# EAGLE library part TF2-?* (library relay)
SMALL POLARIZED RELAY WITH HIGH SENSITIVITY NAiS Source: http://www.mew-europe.com/.. en_ds_61017_0000.pdf
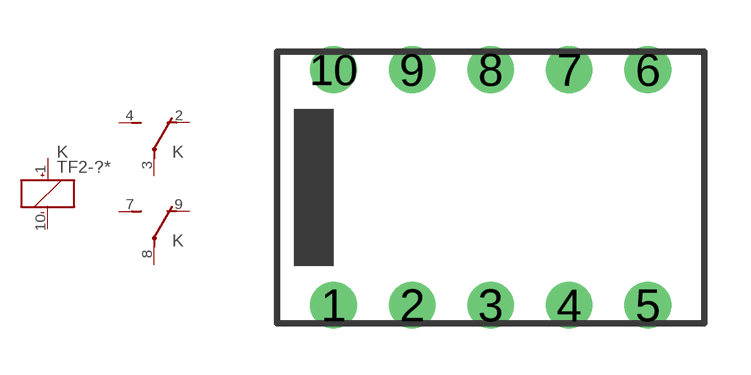
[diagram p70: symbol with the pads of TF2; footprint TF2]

Designator prefix K; gates -=K+- 1=U 2=U

## TF2--3V (OC_FARNELL: unknown; OC_NEWARK: unknown), TF2--4.5V (OC_FARNELL: unknown; OC_NEWARK: unknown), TF2--5V (OC_FARNELL: unknown; OC_NEWARK: unknown), TF2--6V (OC_FARNELL: unknown; OC_NEWARK: unknown), TF2--9V (OC_FARNELL: unknown; OC_NEWARK: unknown), TF2--12V (OC_FARNELL: unknown; OC_NEWARK: unknown), TF2--24V (OC_FARNELL: unknown; OC_NEWARK: unknown), TF2--48V (OC_FARNELL: unknown; OC_NEWARK: unknown)  [TF2]
1  -:+  pas
2  1:O  pas
3  1:P  pas
4  1:S  pas
7  2:S  pas
8  2:P  pas
9  2:O  pas
10  -:-  pas

## TF2-L-3V (OC_FARNELL: unknown; OC_NEWARK: unknown), TF2-L-4.5V (OC_FARNELL: unknown; OC_NEWARK: unknown), TF2-L-5V (OC_FARNELL: unknown; OC_NEWARK: unknown), TF2-L-6V (OC_FARNELL: unknown; OC_NEWARK: unknown), TF2-L-9V (OC_FARNELL: unknown; OC_NEWARK: unknown), TF2-L-12V (OC_FARNELL: 846004; OC_NEWARK: unknown), TF2-L-24V (OC_FARNELL: unknown; OC_NEWARK: unknown)  [TF2]
1  -:-  pas
2  1:O  pas
3  1:P  pas
4  1:S  pas
7  2:S  pas
8  2:P  pas
9  2:O  pas
10  -:+  pas

## Footprint TF2 (pad centres in mm)
SMALL POLARIZED RELAY WITH HIGH SENSITIVITY NAiS Source: http://www.mew-europe.com/.. en_ds_61017_0000.pdf
drill 1 round: 1 -5.08,-3.81; 2 -2.54,-3.81; 3 0,-3.81; 4 2.54,-3.81; 5 5.08,-3.81; 6 5.08,3.81; 7 2.54,3.81; 8 0,3.81; 9 -2.54,3.81; 10 -5.08,3.81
